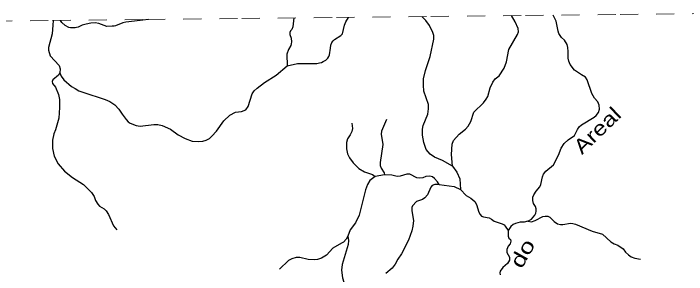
# Model space of a CAD drawing. Extents: x 320.3 to 346.3, y 7455.4 to 7483.3.
# Drawn here: x 336.328 to 340.058, y 7481.838 to 7483.283 of the extents above; entities that cross this region are included whole.
import ezdxf
from ezdxf.enums import TextEntityAlignment as Align

# ---------------------------------------------------------------- set-up
doc = ezdxf.new("R2010")
doc.units = 0
doc.header["$LTSCALE"] = 0.032
doc.linetypes.add('SHORT_DASHED', pattern=[2.7, 1.5, -1.2])
doc.layers.add('53', color=7, linetype='SHORT_DASHED', lineweight=13)
doc.layers.add('7', color=7, linetype='Continuous', lineweight=25)
doc.layers.add('61', color=7, linetype='Continuous')

msp = doc.modelspace()

# ---------------------------------------------------------------- linework, layer by layer
at = {"layer": '53'}
msp.add_lwpolyline([(333.4017, 7483.2096), (333.9256, 7483.2153), (334.4496, 7483.221), (334.9736, 7483.2267), (335.4976, 7483.2324), (336.0216, 7483.238), (336.5456, 7483.2437), (337.0696, 7483.2493), (337.5936, 7483.2549), (338.1176, 7483.2605), (338.6415, 7483.266), (339.1655, 7483.2716), (339.6895, 7483.2771), (340.2135, 7483.2826)], dxfattribs=at)
at = {"layer": '7'}
msp.add_line((338.3846, 7482.3892), (338.3321, 7482.3804), dxfattribs=at)
for points in [[(337.8817, 7483.258), (337.8772, 7483.2093), (337.8702, 7483.1946), (337.8637, 7483.1868), (337.8605, 7483.1779), (337.8597, 7483.1665), (337.8663, 7483.1462), (337.8696, 7483.1263), (337.8676, 7483.1154), (337.8648, 7483.1048), (337.8518, 7483.0829), (337.8434, 7483.058), (337.8453, 7482.9936)], [(337.8453, 7482.9936), (337.9017, 7483.0055), (337.9873, 7483.0061), (338.0089, 7483.0064), (338.0235, 7483.0087), (338.0344, 7483.0107), (338.0448, 7483.0165), (338.0586, 7483.0245), (338.0702, 7483.0344), (338.0756, 7483.0441), (338.0803, 7483.0545), (338.0848, 7483.0909), (338.0874, 7483.1069), (338.0929, 7483.1223), (338.0992, 7483.1318), (338.1075, 7483.1394), (338.1427, 7483.1614), (338.1517, 7483.1704), (338.1634, 7483.2177), (338.1705, 7483.2365), (338.1846, 7483.2612)], [(338.7609, 7482.4377), (338.7048, 7482.4681), (338.6606, 7482.4868), (338.6381, 7482.5032), (338.6158, 7482.5301), (338.6025, 7482.5688), (338.5944, 7482.6087), (338.5945, 7482.642), (338.5992, 7482.6623), (338.6241, 7482.726), (338.6285, 7482.7549), (338.6277, 7482.7789), (338.6029, 7482.8531), (338.5999, 7482.8859), (338.6008, 7482.9205), (338.611, 7482.9663), (338.6376, 7483.0439), (338.6582, 7483.1404), (338.6569, 7483.1601), (338.6514, 7483.1774), (338.6334, 7483.2155), (338.6138, 7483.2435), (338.591, 7483.2655)], [(338.7609, 7482.4377), (338.7551, 7482.5015), (338.7597, 7482.5594), (338.7673, 7482.5804), (338.797, 7482.6151), (338.8322, 7482.6431), (338.8476, 7482.6593), (338.8626, 7482.6853), (338.8788, 7482.7357), (338.9327, 7482.7879), (338.9472, 7482.8077), (338.9559, 7482.8232), (338.9695, 7482.8712), (338.984, 7482.9024), (338.9966, 7482.9206), (339.0191, 7482.937), (339.0473, 7482.9791), (339.0601, 7483.0145), (339.0737, 7483.084), (339.1215, 7483.1654), (339.1267, 7483.1816), (339.1255, 7483.1993), (339.1089, 7483.2364), (339.0879, 7483.2708)], [(339.1791, 7482.1327), (339.1982, 7482.1442), (339.2163, 7482.1672), (339.2222, 7482.1782), (339.2253, 7482.1891), (339.2247, 7482.2024), (339.2201, 7482.2135), (339.2095, 7482.2308), (339.206, 7482.2481), (339.206, 7482.2664), (339.211, 7482.2798), (339.2244, 7482.2994), (339.2452, 7482.3236), (339.2501, 7482.3365), (339.2592, 7482.3788), (339.2646, 7482.3934), (339.2777, 7482.4107), (339.3204, 7482.4454), (339.3476, 7482.4993), (339.3626, 7482.5377), (339.38, 7482.5631), (339.401, 7482.5825), (339.4369, 7482.6082), (339.4407, 7482.6155), (339.4529, 7482.6413), (339.4623, 7482.6555), (339.4755, 7482.6671), (339.5467, 7482.7091), (339.5574, 7482.7181), (339.5696, 7482.7355), (339.5752, 7482.7539), (339.574, 7482.7743), (339.5664, 7482.7935), (339.5473, 7482.8136), (339.5321, 7482.84), (339.5073, 7482.9153), (339.4971, 7482.9296), (339.4752, 7482.9429), (339.4365, 7482.9696), (339.4129, 7483.0001), (339.4048, 7483.0188), (339.4023, 7483.0355), (339.4018, 7483.0722), (339.3996, 7483.0952), (339.3964, 7483.1113), (339.3806, 7483.1344), (339.3645, 7483.1493), (339.3571, 7483.1613), (339.3499, 7483.1726), (339.346, 7483.1855), (339.3361, 7483.2403), (339.3321, 7483.2482), (339.3196, 7483.2732)], [(336.5484, 7483.2437), (336.5464, 7483.2187), (336.5424, 7483.1701), (336.5221, 7483.0943), (336.5225, 7483.0796), (336.5325, 7483.0484), (336.5823, 7482.9956), (336.5874, 7482.9763), (336.5853, 7482.9538)], [(337.076, 7483.2494), (337.0447, 7483.2455), (336.9984, 7483.2399), (336.9513, 7483.2351), (336.9337, 7483.2313), (336.894, 7483.2151), (336.887, 7483.2131), (336.8745, 7483.2122), (336.8461, 7483.2111), (336.8019, 7483.227), (336.782, 7483.2301), (336.7572, 7483.2293), (336.7313, 7483.2236), (336.709, 7483.2173), (336.6874, 7483.2067), (336.6783, 7483.2055), (336.6705, 7483.2038), (336.6454, 7483.2035), (336.6355, 7483.2055), (336.6146, 7483.2169), (336.596, 7483.2326), (336.5894, 7483.2442)], [(336.5853, 7482.9538), (336.5932, 7482.9361), (336.6078, 7482.9155), (336.6495, 7482.8793), (336.6696, 7482.8668), (336.6906, 7482.8554), (336.7123, 7482.8478), (336.8364, 7482.8066), (336.8616, 7482.7955), (336.8901, 7482.7775), (336.9131, 7482.7527), (336.93, 7482.7257), (336.9522, 7482.6953), (336.964, 7482.6835), (336.9754, 7482.6747), (337.0082, 7482.6628), (337.0307, 7482.6593), (337.1071, 7482.6687), (337.1285, 7482.668), (337.1524, 7482.6621), (337.1989, 7482.6416), (337.2405, 7482.6108), (337.2794, 7482.5916), (337.3192, 7482.5764), (337.3549, 7482.5737), (337.3771, 7482.5765), (337.397, 7482.5821), (337.4137, 7482.5915), (337.4274, 7482.6032), (337.4533, 7482.6319), (337.4936, 7482.6878), (337.5274, 7482.7198), (337.558, 7482.7356), (337.5917, 7482.7401), (337.616, 7482.7502), (337.6281, 7482.7681), (337.6509, 7482.8386), (337.6624, 7482.8541), (337.6778, 7482.8695), (337.7193, 7482.9011), (337.7831, 7482.9409), (337.8453, 7482.9936)], [(336.5853, 7482.9538), (336.5771, 7482.9409), (336.5458, 7482.9148), (336.5433, 7482.9059), (336.5452, 7482.8959), (336.5607, 7482.8742), (336.5778, 7482.8333), (336.5827, 7482.8072), (336.5844, 7482.7614), (336.5798, 7482.7036), (336.5617, 7482.6384), (336.5517, 7482.616), (336.5445, 7482.5814), (336.5446, 7482.5358), (336.5536, 7482.493), (336.5768, 7482.4507), (336.611, 7482.4106), (336.6555, 7482.3745), (336.7157, 7482.3362), (336.7601, 7482.2915), (336.7757, 7482.2694), (336.7836, 7482.2467), (336.7953, 7482.2271), (336.8058, 7482.2161), (336.8304, 7482.2015), (336.8427, 7482.1903), (336.8549, 7482.171), (336.8831, 7482.1068), (336.9009, 7482.0858)], [(338.3955, 7482.6955), (338.367, 7482.6313), (338.3663, 7482.6148), (338.3751, 7482.5581), (338.3598, 7482.4588), (338.361, 7482.441), (338.3656, 7482.4257), (338.3824, 7482.4004), (338.3846, 7482.3892)], [(338.2031, 7482.6762), (338.2064, 7482.6468), (338.2033, 7482.6299), (338.1947, 7482.6102), (338.179, 7482.5888), (338.1733, 7482.5694), (338.1729, 7482.5334), (338.1793, 7482.5064), (338.1904, 7482.4833), (338.21, 7482.4569), (338.2422, 7482.4245), (338.2739, 7482.4059), (338.3181, 7482.3915), (338.3321, 7482.3804)], [(338.7609, 7482.4377), (338.7852, 7482.4043), (338.8016, 7482.3681), (338.8045, 7482.3085)], [(338.3321, 7482.3804), (338.3038, 7482.3574), (338.2894, 7482.336), (338.2785, 7482.306), (338.2444, 7482.1669), (338.223, 7482.1236), (338.1939, 7482.0858), (338.181, 7482.0499)], [(338.6873, 7482.3362), (338.6777, 7482.3516), (338.6621, 7482.3685), (338.6495, 7482.3778), (338.6346, 7482.3821), (338.613, 7482.3808), (338.5957, 7482.3734), (338.5787, 7482.3706), (338.5641, 7482.373), (338.5249, 7482.3926), (338.5081, 7482.393), (338.4708, 7482.3823), (338.456, 7482.3809), (338.4464, 7482.383), (338.4248, 7482.3869), (338.3846, 7482.3892)], [(338.6873, 7482.3362), (338.6639, 7482.3362), (338.648, 7482.3302), (338.64, 7482.3221), (338.6219, 7482.2797), (338.608, 7482.2628), (338.5939, 7482.2532), (338.5616, 7482.2415), (338.5401, 7482.2188), (338.5365, 7482.2092), (338.5362, 7482.1897), (338.544, 7482.1369), (338.5407, 7482.106), (338.5351, 7482.0799), (338.5169, 7482.0288), (338.4788, 7481.9523), (338.4582, 7481.9232), (338.4429, 7481.8953), (338.4265, 7481.8728), (338.3915, 7481.8444)], [(338.6873, 7482.3362), (338.7697, 7482.3259), (338.8045, 7482.3085)], [(338.8045, 7482.3085), (338.8363, 7482.2746), (338.8627, 7482.2597), (338.8839, 7482.2423), (338.8943, 7482.2253), (338.9065, 7482.1824), (338.9134, 7482.1701), (338.9216, 7482.1616), (338.9324, 7482.1575), (338.9643, 7482.1515), (338.9775, 7482.1452), (338.9924, 7482.1324), (339.0365, 7482.1185), (339.0465, 7482.1136), (339.0529, 7482.1062), (339.0685, 7482.0811)], [(339.1791, 7482.1327), (339.1986, 7482.1303), (339.2195, 7482.1366), (339.2617, 7482.1595), (339.2752, 7482.1616), (339.29, 7482.1608), (339.3001, 7482.1557), (339.3244, 7482.1308), (339.342, 7482.1191), (339.3592, 7482.1154), (339.372, 7482.1154), (339.4143, 7482.1214), (339.4284, 7482.1212), (339.4421, 7482.1175), (339.5355, 7482.0777), (339.5923, 7482.061), (339.6391, 7482.0185), (339.6575, 7482.0084), (339.6774, 7482.0003), (339.7074, 7481.9803), (339.7198, 7481.9623), (339.7354, 7481.9471), (339.7516, 7481.9357), (339.7706, 7481.9292), (339.8018, 7481.9224)], [(339.1791, 7482.1327), (339.1586, 7482.1285), (339.1353, 7482.1285), (339.1091, 7482.1206), (339.0972, 7482.1148), (339.084, 7482.1032), (339.0685, 7482.0811)], [(339.0685, 7482.0811), (339.0691, 7482.0497), (339.0734, 7482.0385), (339.0817, 7482.0309), (339.0845, 7482.0219), (339.0807, 7482.0078), (339.0702, 7481.9956), (339.0616, 7481.9766), (339.0622, 7481.96), (339.0766, 7481.9345), (339.0762, 7481.9177), (339.0658, 7481.899), (339.0392, 7481.8777), (339.0255, 7481.857), (339.0241, 7481.8479), (339.0251, 7481.8366)], [(338.181, 7482.0499), (338.1725, 7482.0331), (338.1576, 7482.0167), (338.1465, 7482.0107), (338.0979, 7481.9843), (338.0637, 7481.9458), (338.0357, 7481.9286), (338.0122, 7481.9203), (337.9943, 7481.9192), (337.962, 7481.9219), (337.9155, 7481.9324), (337.895, 7481.932), (337.8715, 7481.9249), (337.8524, 7481.9147), (337.8026, 7481.8669)], [(338.181, 7482.0499), (338.1843, 7482.0255), (338.1824, 7482.005), (338.1498, 7481.8941), (338.1468, 7481.8625), (338.1513, 7481.8197), (338.1648, 7481.778), (338.1813, 7481.7427), (338.1908, 7481.7156), (338.1933, 7481.7017), (338.1934, 7481.676), (338.1887, 7481.651), (338.1839, 7481.632)]]:
    msp.add_lwpolyline(points, dxfattribs=at)

# ---------------------------------------------------------------- texts
at = {"layer": '61'}
for s, rotation, width, p in [('Areal', 44.094, 1.25, (339.5904, 7482.6065)), ('do', 60.738, 1.35, (339.1834, 7481.9353))]:
    msp.add_text(s, height=0.08, rotation=rotation, dxfattribs=dict(at, width=width)).set_placement(p, align=Align.CENTER)

doc.saveas('drawing.dxf')
